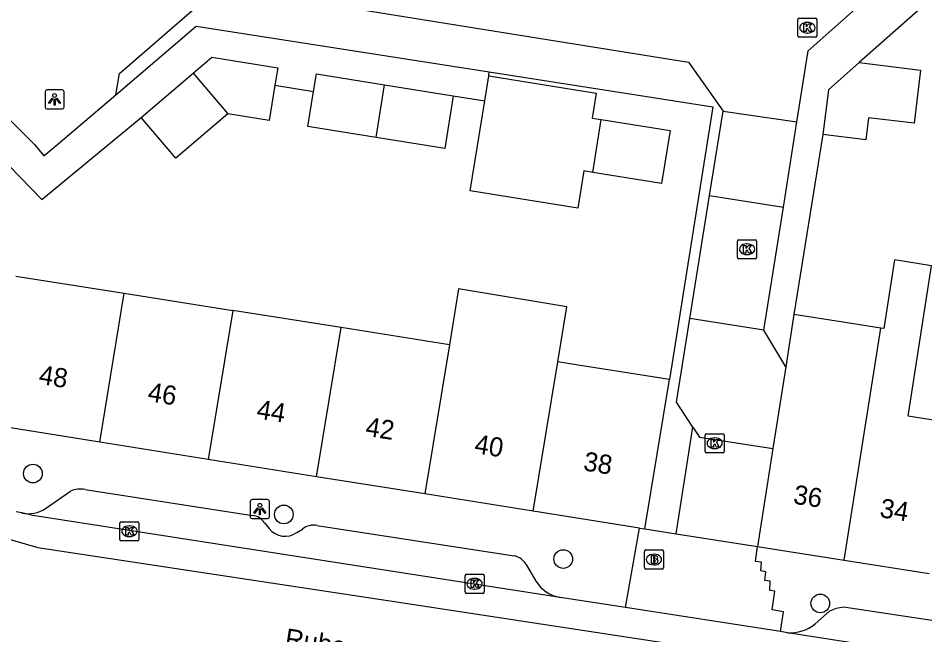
# Model space of a CAD drawing. Extents: x 162172 to 163187, y 382874 to 383684.
# Drawn here: x 162573.41 to 162620.88, y 383337.94 to 383370.26 of the extents above; entities that cross this region are included whole.
import ezdxf

# ---------------------------------------------------------------- set-up
doc = ezdxf.new("R2010")
doc.units = 0
for name, color, linetype in [('IMGEO_Boom', 7, 'Continuous'), ('IMGEO_Brandkraan', 7, 'Continuous'), ('IMGEO_Kolk', 7, 'Continuous'), ('IMGEO_Lichtpunt', 7, 'Continuous'), ('IMGEO_Muur', 7, 'Continuous'), ('IMGEO_Openbare_ruimte_label', 7, 'Continuous'), ('IMGEO_Pand', 7, 'Continuous'), ('IMGEO_Pand_nummerreeks', 7, 'Continuous'), ('IMGEO_Rijbaan_lokaal_gesloten', 7, 'Continuous'), ('IMGEO_Rijbaan_lokaal_open', 7, 'Continuous'), ('IMGEO_Voetpad_open', 7, 'Continuous')]:
    doc.layers.add(name, color=color, linetype=linetype)

msp = doc.modelspace()

# ---------------------------------------------------------------- linework, layer by layer
at = {"layer": 'IMGEO_Boom'}
for centre in [(162574.183, 383346.394), (162587.321, 383344.254), (162601.949, 383341.916), (162615.409, 383339.591)]:
    msp.add_circle(centre, 0.489, dxfattribs=at)
at = {"layer": 'IMGEO_Brandkraan'}
for p, q in [((162606.198, 383341.466), (162606.198, 383342.318)), ((162606.273, 383342.392), (162607.125, 383342.392)), ((162606.686, 383342.172), (162606.711, 383342.172)), ((162607.199, 383342.318), (162607.199, 383341.466)), ((162606.709, 383341.612), (162606.684, 383341.612)), ((162607.125, 383341.392), (162606.273, 383341.392))]:
    msp.add_line(p, q, dxfattribs=at)
for points in [[(162606.198, 383341.466), (162606.198, 383342.318)], [(162606.273, 383342.392), (162607.125, 383342.392)], [(162606.546, 383342.092), (162606.546, 383341.692), (162606.759, 383341.692)], [(162606.777, 383342.092), (162606.546, 383342.092)], [(162607.199, 383342.318), (162607.199, 383341.466)], [(162606.725, 383342.011), (162606.671, 383342.011), (162606.671, 383341.935)], [(162606.671, 383341.935), (162606.724, 383341.935)], [(162606.733, 383341.859), (162606.671, 383341.859), (162606.671, 383341.778)], [(162606.671, 383341.778), (162606.733, 383341.778)], [(162607.125, 383341.392), (162606.273, 383341.392)]]:
    msp.add_lwpolyline(points, dxfattribs=at)
for centre, radius, start, end in [((162606.275, 383342.316), 0.0765, 91.552, 178.448), ((162606.275, 383342.316), 0.0765, 91.552, 178.448), ((162606.781, 383341.947), 0.145, 59.4692, 91.5367), ((162607.123, 383342.316), 0.0765, 1.552, 88.448), ((162607.123, 383342.316), 0.0765, 1.552, 88.448), ((162606.726, 383341.973), 0.0379, 267.8285, 90.9355), ((162606.734, 383341.818), 0.0404, 269.8759, 90.5077), ((162606.765, 383341.943), 0.251, 268.6676, 293.5347), ((162606.806, 383341.994), 0.0922, 285.5137, 58.1501), ((162606.811, 383341.802), 0.105, 301.3115, 78.989), ((162606.275, 383341.468), 0.0765, 181.552, 268.448), ((162606.275, 383341.468), 0.0765, 181.552, 268.448), ((162607.123, 383341.468), 0.0765, 271.552, 358.448), ((162607.123, 383341.468), 0.0765, 271.552, 358.448)]:
    msp.add_arc(centre, radius, start, end, dxfattribs=at)
for centre, major_axis, ratio, start_param, end_param in [((162606.685, 383341.892), (-0.387, 0.002), 0.722429, 4.712389, 7.853982), ((162606.71, 383341.892), (-0.39, 0.002), 0.717154, 1.570796, 4.712389)]:
    msp.add_ellipse(centre, major_axis=major_axis, ratio=ratio, start_param=start_param, end_param=end_param, dxfattribs=at)
at = {"layer": 'IMGEO_Kolk'}
for p, q in [((162614.23, 383369.329), (162614.23, 383370.181)), ((162614.305, 383370.255), (162615.157, 383370.255)), ((162615.231, 383370.181), (162615.231, 383369.329)), ((162614.718, 383370.035), (162614.743, 383370.035)), ((162615.157, 383369.255), (162614.305, 383369.255)), ((162614.741, 383369.475), (162614.716, 383369.475)), ((162611.074, 383357.719), (162611.074, 383358.571)), ((162611.149, 383358.645), (162612.001, 383358.645)), ((162611.562, 383358.425), (162611.587, 383358.425)), ((162612.075, 383358.571), (162612.075, 383357.719)), ((162611.585, 383357.865), (162611.56, 383357.865)), ((162612.001, 383357.645), (162611.149, 383357.645)), ((162609.377, 383347.558), (162609.377, 383348.41)), ((162609.452, 383348.484), (162610.304, 383348.484)), ((162609.865, 383348.264), (162609.89, 383348.264)), ((162610.378, 383348.41), (162610.378, 383347.558)), ((162610.304, 383347.484), (162609.452, 383347.484)), ((162609.888, 383347.704), (162609.863, 383347.704)), ((162578.733, 383342.948), (162578.733, 383343.8)), ((162578.808, 383343.874), (162579.66, 383343.874)), ((162579.221, 383343.654), (162579.246, 383343.654)), ((162579.734, 383343.8), (162579.734, 383342.948)), ((162579.244, 383343.094), (162579.219, 383343.094)), ((162579.66, 383342.874), (162578.808, 383342.874)), ((162596.807, 383340.193), (162596.807, 383341.045)), ((162596.882, 383341.119), (162597.734, 383341.119)), ((162597.295, 383340.899), (162597.32, 383340.899)), ((162597.808, 383341.045), (162597.808, 383340.193)), ((162597.318, 383340.339), (162597.293, 383340.339)), ((162597.734, 383340.119), (162596.882, 383340.119))]:
    msp.add_line(p, q, dxfattribs=at)
for points in [[(162614.23, 383369.329), (162614.23, 383370.181)], [(162614.305, 383370.255), (162615.157, 383370.255)], [(162615.231, 383370.181), (162615.231, 383369.329)], [(162614.551, 383369.955), (162614.674, 383369.955), (162614.674, 383369.804), (162614.804, 383369.955), (162614.968, 383369.955), (162614.822, 383369.804), (162614.975, 383369.555), (162614.823, 383369.555), (162614.738, 383369.719), (162614.674, 383369.652), (162614.674, 383369.555), (162614.551, 383369.555), (162614.551, 383369.955)], [(162615.157, 383369.255), (162614.305, 383369.255)], [(162611.074, 383357.719), (162611.074, 383358.571)], [(162611.149, 383358.645), (162612.001, 383358.645)], [(162611.395, 383358.345), (162611.518, 383358.345), (162611.518, 383358.194), (162611.648, 383358.345), (162611.812, 383358.345), (162611.666, 383358.194), (162611.819, 383357.945), (162611.667, 383357.945), (162611.582, 383358.109), (162611.518, 383358.042), (162611.518, 383357.945), (162611.395, 383357.945), (162611.395, 383358.345)], [(162612.075, 383358.571), (162612.075, 383357.719)], [(162612.001, 383357.645), (162611.149, 383357.645)], [(162609.377, 383347.558), (162609.377, 383348.41)], [(162609.452, 383348.484), (162610.304, 383348.484)], [(162610.378, 383348.41), (162610.378, 383347.558)], [(162609.698, 383348.184), (162609.821, 383348.184), (162609.821, 383348.033), (162609.951, 383348.184), (162610.115, 383348.184), (162609.969, 383348.033), (162610.122, 383347.784), (162609.97, 383347.784), (162609.885, 383347.948), (162609.821, 383347.881), (162609.821, 383347.784), (162609.698, 383347.784), (162609.698, 383348.184)], [(162610.304, 383347.484), (162609.452, 383347.484)], [(162578.733, 383342.948), (162578.733, 383343.8)], [(162578.808, 383343.874), (162579.66, 383343.874)], [(162579.054, 383343.574), (162579.177, 383343.574), (162579.177, 383343.423), (162579.307, 383343.574), (162579.471, 383343.574), (162579.325, 383343.423), (162579.478, 383343.174), (162579.326, 383343.174), (162579.241, 383343.338), (162579.177, 383343.271), (162579.177, 383343.174), (162579.054, 383343.174), (162579.054, 383343.574)], [(162579.734, 383343.8), (162579.734, 383342.948)], [(162579.66, 383342.874), (162578.808, 383342.874)], [(162596.807, 383340.193), (162596.807, 383341.045)], [(162596.882, 383341.119), (162597.734, 383341.119)], [(162597.128, 383340.819), (162597.251, 383340.819), (162597.251, 383340.668), (162597.381, 383340.819), (162597.545, 383340.819), (162597.399, 383340.668), (162597.552, 383340.419), (162597.4, 383340.419), (162597.315, 383340.583), (162597.251, 383340.516), (162597.251, 383340.419), (162597.128, 383340.419), (162597.128, 383340.819)], [(162597.808, 383341.045), (162597.808, 383340.193)], [(162597.734, 383340.119), (162596.882, 383340.119)]]:
    msp.add_lwpolyline(points, dxfattribs=at)
for centre, start, end in [((162614.307, 383370.179), 91.552, 178.448), ((162614.307, 383370.179), 91.552, 178.448), ((162615.155, 383370.179), 1.552, 88.448), ((162615.155, 383370.179), 1.552, 88.448), ((162614.307, 383369.331), 181.552, 268.448), ((162614.307, 383369.331), 181.552, 268.448), ((162615.155, 383369.331), 271.552, 358.448), ((162615.155, 383369.331), 271.552, 358.448), ((162611.151, 383358.569), 91.552, 178.448), ((162611.151, 383358.569), 91.552, 178.448), ((162611.999, 383358.569), 1.552, 88.448), ((162611.999, 383358.569), 1.552, 88.448), ((162611.151, 383357.721), 181.552, 268.448), ((162611.151, 383357.721), 181.552, 268.448), ((162611.999, 383357.721), 271.552, 358.448), ((162611.999, 383357.721), 271.552, 358.448), ((162609.454, 383348.408), 91.552, 178.448), ((162609.454, 383348.408), 91.552, 178.448), ((162610.302, 383348.408), 1.552, 88.448), ((162610.302, 383348.408), 1.552, 88.448), ((162609.454, 383347.56), 181.552, 268.448), ((162609.454, 383347.56), 181.552, 268.448), ((162610.302, 383347.56), 271.552, 358.448), ((162610.302, 383347.56), 271.552, 358.448), ((162578.81, 383343.798), 91.552, 178.448), ((162578.81, 383343.798), 91.552, 178.448), ((162579.658, 383343.798), 1.552, 88.448), ((162579.658, 383343.798), 1.552, 88.448), ((162578.81, 383342.95), 181.552, 268.448), ((162578.81, 383342.95), 181.552, 268.448), ((162579.658, 383342.95), 271.552, 358.448), ((162579.658, 383342.95), 271.552, 358.448), ((162596.884, 383341.043), 91.552, 178.448), ((162596.884, 383341.043), 91.552, 178.448), ((162597.732, 383341.043), 1.552, 88.448), ((162597.732, 383341.043), 1.552, 88.448), ((162596.884, 383340.195), 181.552, 268.448), ((162596.884, 383340.195), 181.552, 268.448), ((162597.732, 383340.195), 271.552, 358.448), ((162597.732, 383340.195), 271.552, 358.448)]:
    msp.add_arc(centre, 0.0765, start, end, dxfattribs=at)
for centre, major_axis, ratio, start_param, end_param in [((162614.717, 383369.755), (-0.387, 0.002), 0.722429, 4.712389, 7.853982), ((162614.742, 383369.755), (-0.39, 0.002), 0.717154, 1.570796, 4.712389), ((162611.561, 383358.145), (-0.387, 0.002), 0.722429, 4.712389, 7.853982), ((162611.586, 383358.145), (-0.39, 0.002), 0.717154, 1.570796, 4.712389), ((162609.864, 383347.984), (-0.387, 0.002), 0.722429, 4.712389, 7.853982), ((162609.889, 383347.984), (-0.39, 0.002), 0.717154, 1.570796, 4.712389), ((162579.22, 383343.374), (-0.387, 0.002), 0.722429, 4.712389, 7.853982), ((162579.245, 383343.374), (-0.39, 0.002), 0.717154, 1.570796, 4.712389), ((162597.294, 383340.619), (-0.387, 0.002), 0.722429, 4.712389, 7.853982), ((162597.319, 383340.619), (-0.39, 0.002), 0.717154, 1.570796, 4.712389)]:
    msp.add_ellipse(centre, major_axis=major_axis, ratio=ratio, start_param=start_param, end_param=end_param, dxfattribs=at)
at = {"layer": 'IMGEO_Lichtpunt'}
for p, q in [((162574.819, 383366.401), (162574.819, 383365.594)), ((162574.819, 383366.401), (162574.819, 383365.594)), ((162575.721, 383366.496), (162574.913, 383366.496)), ((162575.721, 383366.496), (162574.913, 383366.496)), ((162575.815, 383365.594), (162575.815, 383366.401)), ((162575.815, 383365.594), (162575.815, 383366.401)), ((162574.913, 383365.5), (162575.721, 383365.5)), ((162574.913, 383365.5), (162575.721, 383365.5)), ((162585.566, 383344.935), (162585.566, 383344.128)), ((162585.566, 383344.935), (162585.566, 383344.128)), ((162586.468, 383345.03), (162585.66, 383345.03)), ((162586.468, 383345.03), (162585.66, 383345.03)), ((162586.562, 383344.128), (162586.562, 383344.935)), ((162586.562, 383344.128), (162586.562, 383344.935)), ((162585.66, 383344.034), (162586.468, 383344.034)), ((162585.66, 383344.034), (162586.468, 383344.034))]:
    msp.add_line(p, q, dxfattribs=at)
for points in [[(162575.193, 383366.065), (162575.232, 383366.037), (162575.044, 383365.775), (162575.006, 383365.802), (162575.193, 383366.065)], [(162575.295, 383366.017), (162575.342, 383366.017), (162575.342, 383365.695), (162575.295, 383365.695), (162575.295, 383366.017)], [(162575.405, 383366.037), (162575.443, 383366.064), (162575.63, 383365.802), (162575.591, 383365.774), (162575.405, 383366.037)], [(162585.94, 383344.599), (162585.979, 383344.571), (162585.791, 383344.309), (162585.753, 383344.336), (162585.94, 383344.599)], [(162586.042, 383344.551), (162586.089, 383344.551), (162586.089, 383344.229), (162586.042, 383344.229), (162586.042, 383344.551)], [(162586.152, 383344.571), (162586.19, 383344.598), (162586.377, 383344.336), (162586.338, 383344.308), (162586.152, 383344.571)]]:
    msp.add_lwpolyline(points, dxfattribs=at)
for centre in [(162575.318, 383366.199), (162586.065, 383344.733)]:
    msp.add_circle(centre, 0.0994, dxfattribs=at)
for centre, start, end in [((162574.913, 383366.401), 90, 180), ((162574.913, 383366.401), 90, 180), ((162575.721, 383366.401), 0, 90), ((162575.721, 383366.401), 0, 90), ((162574.913, 383365.594), 180, 270), ((162574.913, 383365.594), 180, 270), ((162575.721, 383365.594), 270, 0), ((162575.721, 383365.594), 270, 360), ((162585.66, 383344.935), 90, 180), ((162585.66, 383344.935), 90, 180), ((162586.468, 383344.935), 0, 90), ((162586.468, 383344.935), 0, 90), ((162585.66, 383344.128), 180, 270), ((162585.66, 383344.128), 180, 270), ((162586.468, 383344.128), 270, 0), ((162586.468, 383344.128), 270, 360)]:
    msp.add_arc(centre, 0.0946, start, end, dxfattribs=at)
at = {"layer": 'IMGEO_Muur'}
msp.add_lwpolyline([(162609.776, 383365.605), (162607.511, 383351.322)], dxfattribs=at)
at = {"layer": 'IMGEO_Pand'}
for points in [[(162582.568, 383367.374), (162583.548, 383368.213), (162587.004, 383367.659), (162586.857, 383366.741)], [(162617.443, 383367.922), (162620.662, 383367.527), (162620.321, 383364.746), (162617.93, 383365.039), (162617.788, 383363.881), (162615.547, 383364.155)], [(162617.443, 383367.922), (162615.835, 383366.501), (162615.547, 383364.155)], [(162579.85, 383365.046), (162582.568, 383367.374)], [(162582.568, 383367.374), (162584.392, 383365.243)], [(162588.881, 383366.416), (162589.028, 383367.335), (162592.593, 383366.764)], [(162597.837, 383365.923), (162598.047, 383367.229)], [(162598.047, 383367.229), (162603.675, 383366.321), (162603.465, 383365.018), (162603.939, 383364.942)], [(162586.857, 383366.741), (162586.561, 383364.895), (162584.392, 383365.243)], [(162592.15, 383363.997), (162588.585, 383364.57), (162588.881, 383366.416)], [(162592.15, 383363.997), (162592.593, 383366.764)], [(162592.593, 383366.764), (162596.188, 383366.188)], [(162596.188, 383366.188), (162595.744, 383363.42), (162592.15, 383363.997)], [(162603.495, 383362.176), (162603.021, 383362.252), (162602.708, 383360.298), (162597.08, 383361.206), (162597.837, 383365.923)], [(162584.392, 383365.243), (162581.672, 383362.92), (162579.85, 383365.046)], [(162603.939, 383364.942), (162607.541, 383364.361), (162607.098, 383361.597), (162603.495, 383362.176)], [(162603.495, 383362.176), (162603.939, 383364.942)], [(162622.318, 383349.033), (162620.003, 383349.397), (162620.677, 383353.683), (162621.234, 383357.282), (162619.292, 383357.587), (162618.734, 383353.989), (162618.578, 383354.014)], [(162573.297, 383356.738), (162578.97, 383355.84)], [(162601.664, 383352.248), (162602.138, 383355.137), (162596.469, 383356.067), (162595.99, 383353.146)], [(162577.691, 383348.037), (162578.97, 383355.84)], [(162578.97, 383355.84), (162584.644, 383354.942)], [(162584.644, 383354.942), (162583.364, 383347.134)], [(162590.317, 383354.044), (162584.644, 383354.942)], [(162614.027, 383354.729), (162613.597, 383351.992)], [(162618.578, 383354.014), (162616.479, 383354.344), (162614.027, 383354.729)], [(162589.037, 383346.232), (162590.317, 383354.044)], [(162595.99, 383353.146), (162590.317, 383354.044)], [(162616.662, 383341.851), (162618.578, 383354.014)], [(162595.99, 383353.146), (162594.709, 383345.33)], [(162600.381, 383344.427), (162601.664, 383352.248)], [(162607.511, 383351.322), (162602.725, 383352.08), (162601.664, 383352.248)], [(162613.597, 383351.992), (162613.353, 383350.441), (162612.922, 383347.704)], [(162606.229, 383343.497), (162607.511, 383351.322)], [(162577.691, 383348.037), (162572.018, 383348.939)], [(162583.364, 383347.134), (162577.691, 383348.037)], [(162612.922, 383347.704), (162612.113, 383342.567)], [(162589.037, 383346.232), (162583.364, 383347.134)], [(162594.709, 383345.33), (162589.037, 383346.232)], [(162600.381, 383344.427), (162594.709, 383345.33)], [(162605.947, 383343.542), (162600.381, 383344.427)], [(162605.947, 383343.542), (162606.229, 383343.497)], [(162612.113, 383342.567), (162616.662, 383341.851)], [(162616.662, 383341.851), (162621.104, 383341.152)]]:
    msp.add_lwpolyline(points, dxfattribs=at)
at = {"layer": 'IMGEO_Rijbaan_lokaal_gesloten'}
for points in [[(162529.068, 383389.331), (162532.979, 383384.867), (162547.857, 383367.645), (162564.078, 383348.944), (162566.493, 383346.567), (162567.778, 383345.671), (162569.764, 383344.268), (162572.023, 383343.216), (162574.438, 383342.515), (162592.762, 383339.748), (162610.619, 383337.021), (162627.21, 383334.45), (162667.305, 383328.139)], [(162573.598, 383344.329), (162573.305, 383344.396)], [(162601.788, 383339.9), (162574.971, 383344.078), (162574.184, 383344.194), (162573.598, 383344.329)], [(162605.204, 383339.371), (162601.788, 383339.9)], [(162613.319, 383338.115), (162605.204, 383339.371)], [(162613.69, 383338.058), (162613.319, 383338.115)], [(162650.713, 383332.282), (162613.69, 383338.058)]]:
    msp.add_lwpolyline(points, dxfattribs=at)
at = {"layer": 'IMGEO_Rijbaan_lokaal_open'}
for points in [[(162614.183, 383364.828), (162614.769, 383368.544), (162621.775, 383374.778), (162624.11, 383374.55), (162647.002, 383393.986)], [(162578.52, 383366.243), (162578.711, 383367.361), (162583.958, 383371.911), (162586.743, 383371.46), (162608.501, 383367.951), (162610.322, 383365.389)], [(162569.735, 383368.176), (162574.27, 383363.636), (162574.756, 383363.046), (162575.389, 383363.568), (162578.52, 383366.243)], [(162609.611, 383360.96), (162610.322, 383365.389)], [(162610.322, 383365.389), (162614.183, 383364.828)], [(162613.476, 383360.351), (162614.183, 383364.828)], [(162608.576, 383354.512), (162609.611, 383360.96)], [(162609.611, 383360.96), (162613.476, 383360.351)], [(162612.458, 383353.901), (162613.476, 383360.351)], [(162608.741, 383348.818), (162607.873, 383350.136), (162608.576, 383354.512)], [(162612.458, 383353.901), (162608.576, 383354.512)], [(162613.597, 383351.992), (162612.458, 383353.901)], [(162607.861, 383343.239), (162608.741, 383348.818)], [(162608.741, 383348.818), (162609.076, 383348.309), (162612.922, 383347.704)], [(162607.861, 383343.239), (162612.113, 383342.567)]]:
    msp.add_lwpolyline(points, dxfattribs=at)
at = {"layer": 'IMGEO_Voetpad_open'}
for points in [[(162631.275, 383379.318), (162630.629, 383379.573), (162617.443, 383367.922)], [(162578.52, 383366.243), (162582.733, 383369.842), (162598.08, 383367.437)], [(162598.047, 383367.229), (162598.08, 383367.437)], [(162598.08, 383367.437), (162609.776, 383365.605), (162607.511, 383351.322)], [(162586.857, 383366.741), (162588.881, 383366.416)], [(162567.562, 383364.252), (162569.514, 383366.031), (162574.642, 383360.756), (162579.85, 383365.046)], [(162596.188, 383366.188), (162597.837, 383365.923)], [(162615.547, 383364.155), (162614.027, 383354.729)], [(162574.842, 383344.56), (162576.143, 383345.469)], [(162576.918, 383345.564), (162585.679, 383344.205)], [(162586.317, 383343.812), (162586.557, 383343.519)], [(162589.058, 383343.676), (162599.379, 383342.091)], [(162605.204, 383339.371), (162605.947, 383343.542)], [(162587.997, 383343.311), (162588.294, 383343.487)], [(162606.229, 383343.497), (162607.861, 383343.239)], [(162613.319, 383338.115), (162613.475, 383339.146), (162612.88, 383339.249), (162613.024, 383340.229), (162612.758, 383340.271), (162612.792, 383340.762), (162612.505, 383340.791), (162612.552, 383341.243), (162612.287, 383341.301), (162612.337, 383341.748), (162612.007, 383341.781), (162612.113, 383342.567)], [(162600.016, 383341.625), (162600.517, 383340.762)], [(162628.763, 383337.558), (162616.63, 383339.398), (162616.234, 383339.327), (162615.897, 383339.183), (162615.139, 383338.525)]]:
    msp.add_lwpolyline(points, dxfattribs=at)
for centre, radius, start, end in [((162576.693, 383344.191), 1.392, 80.6975, 113.2795), ((162573.943, 383345.936), 1.644, 257.8857, 303.1533), ((162585.577, 383343.325), 0.886, 33.3554, 83.3796), ((162587.383, 383344.15), 1.039, 217.3661, 306.1955), ((162588.885, 383342.737), 0.955, 79.5485, 128.2415), ((162599.122, 383341.072), 1.051, 31.7576, 75.8674), ((162602.13, 383341.773), 1.904, 212.0714, 259.6379), ((162613.852, 383340.036), 1.984, 265.3078, 310.4195)]:
    msp.add_arc(centre, radius, start, end, dxfattribs=at)

# ---------------------------------------------------------------- texts
at = {"layer": 'IMGEO_Openbare_ruimte_label'}
msp.add_text('Rubensstraat', height=1, rotation=351.3758, dxfattribs=at).set_placement((162587.332, 383337.303))
at = {"layer": 'IMGEO_Pand_nummerreeks'}
for s, rotation, p in [('48', 350.9616, (162574.451, 383351.103)), ('46', 350.9616, (162580.151, 383350.197)), ('44', 350.9616, (162585.853, 383349.29)), ('42', 350.9616, (162591.552, 383348.383)), ('40', 350.9616, (162597.259, 383347.475)), ('38', 350.9616, (162602.961, 383346.568)), ('36', 351.0555, (162613.953, 383344.828)), ('34', 351.0555, (162618.481, 383344.116))]:
    msp.add_text(s, height=1, rotation=rotation, dxfattribs=at).set_placement(p)

doc.saveas('drawing.dxf')
